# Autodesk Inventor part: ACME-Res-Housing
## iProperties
Company: Autodesk, Inc.
Shininess: 64.0
Length Units: 11269
Angle Units: 11279
Time Units: 11290
Mass Units: 11283
Length Display Precision: 3
Angle Display Precision: 2
Compacted: True
Part Number: ACME-Res-Housing
Document SubType Name: Modeling
Created: 2003-11
Catalog Web Link: www.autodesk.com
Vendor: Autodesk, Inc.
Designer: Administrator
Manufacturer: Standard
Standards Organization: Custom
Density: 1 g/cm^3
Density: 0.0
Volumn: 0.0
Area: 0.0
PropertySet Name: Model Information
Control State: 0
Master: False
Checked Out: False
Author: Administrator
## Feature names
1. Extrusion1
2. Extrusion2
3. Mirror1
4. Hole1
5. Extrusion4
6. Mirror2
7. Chamfer1
8. Chamfer2
9. Fillet1
10. Revolution1
11. Extrusion7
12. Extrusion8
13. Extrusion9
14. Extrusion10
15. Fillet2
16. Fillet3
17. Extrusion11
18. Revolution2
19. Revolution3
20. Hole3
